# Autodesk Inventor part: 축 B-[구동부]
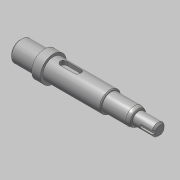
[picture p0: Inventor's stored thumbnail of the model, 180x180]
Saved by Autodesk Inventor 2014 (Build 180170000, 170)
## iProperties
Created: 2020-04
Part Number: 축 B-[구동부]
Material: 강철, 연강
Document SubType Name: Modeling
Designer: mduedu
Density: 7.86 g/cm^3
Appearance: 강철
Mass: 60.8547 g
Surface Area: 31.2855 cm^2
Volume: 7.74232 cm^3
Author: mduedu
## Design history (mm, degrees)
sketch "스케치1"
  geometry: L1 (0, 0)-(14, 0); L2 (14, 0)-(14, 6); L3 (14, 6)-(0, 6); L4 (0, 6)-(0, 0); L5 (14, 0)-(19, 0); L6 (19, 0)-(19, 7.5); L7 (19, 7.5)-(14, 7.5); L8 (14, 7.5)-(14, 0); L9 (19, 0)-(52, 0); L10 (52, 0)-(52, 6); L11 (52, 6)-(19, 6); L12 (19, 6)-(19, 0); L13 (52, 0)-(68, 0); L14 (68, 0)-(68, 5); L15 (68, 5)-(52, 5); L16 (52, 5)-(52, 0); L17 (68, 0)-(80, 0); L18 (80, 0)-(80, 3.5); L19 (80, 3.5)-(68, 3.5); L20 (68, 3.5)-(68, 0)
  constraints: 40 end point, 10 parallel, 5 horizontal, 5 perpendicular
  dimensions: "d0" = 80 distance between parallel lines of L18 L4; "d2" = 14 distance of L2.end L3.end; "d3" = 5 distance of L6.end L7.end; "d5" = 7 diameter of L19 L17; "d6" = 10 diameter of L15 L13; "d7" = 12 diameter of L11 L9; "d8" = 12 diameter of L3 L1; "d9" = 15 diameter of L7 L5; "d35" = 16 distance of L14.end L15.end; "d36" = 52 distance between parallel lines of L10 L4
revolve "회전1" sketch "스케치1" stored, may be unused: angle "d11" = 90 deg
sketch "스케치2"
  geometry: L1 (0, 6)-(0, -6) reference; L2 (0, -6)-(-14, -6) reference; L3 (-14, -6)-(-14, -7.5) reference; L4 (-14, -7.5)-(-19, -7.5) reference; L5 (-19, -7.5)-(-19, -6) reference; L6 (-19, -6)-(-52, -6) reference; L7 (-52, -6)-(-52, -5) reference; L8 (-52, -5)-(-68, -5) reference; L9 (-68, -5)-(-68, -3.5) reference; L10 (-68, -3.5)-(-80, -3.5) reference; L11 (-80, -3.5)-(-80, 3.5) reference; L12 (-80, 3.5)-(-68, 3.5) reference; L13 (-68, 3.5)-(-68, 5) reference; L14 (-68, 5)-(-52, 5) reference; L15 (-52, 5)-(-52, 6) reference; L16 (-52, 6)-(-19, 6) reference; L17 (-19, 6)-(-19, 7.5) reference; L18 (-19, 7.5)-(-14, 7.5) reference; L19 (-14, 7.5)-(-14, 6) reference; L20 (-14, 6)-(0, 6) reference; L21 (-80, 3.5)-(-72, 3.5); L22 (-72, 3.5)-(-72, 2.3); L23 (-72, 2.3)-(-80, 2.3); L24 (-80, 2.3)-(-80, 3.5); 1 further point
  constraints: 8 end point, 2 parallel, 1 horizontal, 1 perpendicular
  dimensions: "d37" = 8 distance of L22.end L23.end; "d38" = 1.2 distance of L21.end L22.end
extrude "돌출1" cut sketch "스케치2" stored distance "d14" = 2; taper "d15" = 0 deg
fillet "모깎기1" dims "d16" = 1
sketch "스케치3"
  geometry: L1 (0, -6)-(0, 6) reference; L2 (0, 6)-(14, 6) reference; L3 (14, 6)-(14, 7.5) reference; L4 (14, 7.5)-(19, 7.5) reference; L5 (19, 7.5)-(19, 6) reference; L6 (19, 6)-(52, 6) reference; L7 (52, 6)-(52, 5) reference; L8 (52, 5)-(68, 5) reference; L9 (68, 5)-(68, 3.5) reference; L10 (68, 3.5)-(80, 3.5) reference; L11 (80, 3.5)-(80, -3.5) reference; L12 (80, -3.5)-(68, -3.5) reference; L13 (68, -3.5)-(68, -5) reference; L14 (68, -5)-(52, -5) reference; L15 (52, -5)-(52, -6) reference; L16 (52, -6)-(19, -6) reference; L17 (19, -6)-(19, -7.5) reference; L18 (19, -7.5)-(14, -7.5) reference; L19 (14, -7.5)-(14, -6) reference; L20 (14, -6)-(0, -6) reference; L21 (23, 6)-(35, 6); L22 (35, 6)-(35, 3.5); L23 (35, 3.5)-(23, 3.5); L24 (23, 3.5)-(23, 6); 1 further point
  constraints: 8 end point, 2 parallel, 1 horizontal, 1 perpendicular, 1 point on line
  dimensions: "d17" = 12 distance of L22.end L23.end; "d18" = 2.5 distance of L21.end L22.end; "d19" = 4 distance from line of L24 L4.end
extrude "돌출2" cut sketch "스케치3" stored distance "d20" = 4; taper "d21" = 0 deg
fillet "모깎기2" dims "d22" = 2
chamfer "모따기1" distance "d23" = 1; stored, may be unused: second distance "d24" = 2, angle "d25" = 45 deg
chamfer "모따기2" distance "d26" = 0.5; stored, may be unused: second distance "d27" = 2, angle "d28" = 45 deg
fillet "모깎기3" dims "d29" = 0.3
chamfer "모따기3" distance "d30" = 1.39; stored, may be unused: second distance "d31" = 2, angle "d32" = 30 deg
fillet "모깎기4" dims "d33" = 4, "d34" = 0.5
node "솔리드1"
node "절단 모서리 투영2"
node "절단 모서리 투영3"
